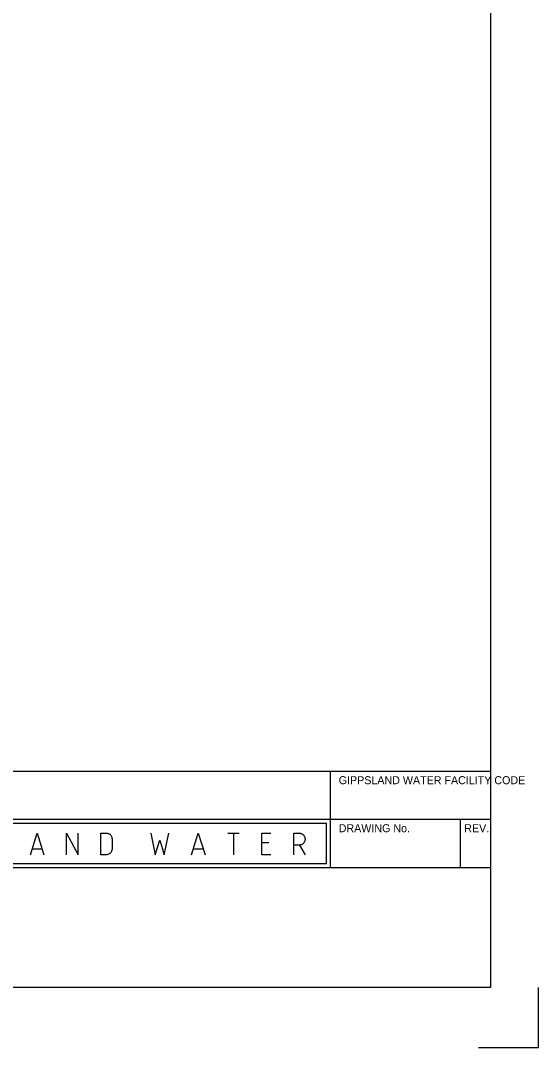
# Model space of a CAD drawing. Extents: x 0 to 841, y 0 to 594.
# Drawn here: x 711.5 to 841, y 0 to 256.6 of the extents above; entities that cross this region are included whole.
import ezdxf

# ---------------------------------------------------------------- set-up
doc = ezdxf.new("R2010")
doc.units = 0
doc.layers.add('A1BORDER', color=7, linetype='Continuous')

msp = doc.modelspace()

# ---------------------------------------------------------------- linework, layer by layer
at = {"layer": 'A1BORDER'}
for p, q in [((829, 581), (829, 15)), ((592.5, 69), (829, 69)), ((789, 45), (789, 69)), ((28, 57), (829, 57)), ((821.5, 45), (821.5, 57)), ((637, 56), (788, 56)), ((788, 46), (788, 56)), ((663, 46), (788, 46)), ((664, 45), (829, 45)), ((829, 15), (28, 15)), ((829, 15), (829, 15)), ((841, 0), (841, 15)), ((826, 0), (841, 0))]:
    msp.add_line(p, q, dxfattribs=at)
for points in [[(713.91, 48.16), (715.61, 53.54), (717.32, 48.16)], [(722.99, 48.16), (722.99, 53.54), (725.83, 48.16), (725.83, 53.54)], [(731.52, 48.16), (731.52, 53.54), (732.94, 53.54), (733.06, 53.54), (733.18, 53.52), (733.3, 53.49), (733.42, 53.45), (733.53, 53.4), (733.64, 53.34), (733.75, 53.27), (733.84, 53.19), (733.94, 53.1), (734.02, 53), (734.09, 52.9), (734.16, 52.79), (734.22, 52.67), (734.27, 52.56), (734.31, 52.43), (734.33, 52.31), (734.35, 52.18), (734.36, 52.05), (734.36, 49.66), (734.35, 49.52), (734.33, 49.39), (734.31, 49.27), (734.27, 49.14), (734.22, 49.02), (734.16, 48.91), (734.09, 48.8), (734.02, 48.7), (733.94, 48.6), (733.84, 48.51), (733.75, 48.43), (733.64, 48.36), (733.53, 48.3), (733.42, 48.25), (733.3, 48.21), (733.18, 48.18), (733.06, 48.16), (732.94, 48.16), (731.52, 48.16)], [(744.01, 53.54), (745.14, 48.16), (746.28, 51.75), (747.41, 48.16), (748.55, 53.54)], [(754.22, 48.16), (755.92, 53.54), (757.63, 48.16)], [(763.31, 53.54), (766.15, 53.54)], [(764.73, 53.54), (764.73, 48.16)], [(774.09, 48.16), (771.82, 48.16), (771.82, 53.54), (774.09, 53.54)], [(779.78, 48.16), (779.78, 53.54), (781.2, 53.54), (781.32, 53.54), (781.44, 53.52), (781.56, 53.49), (781.68, 53.45), (781.79, 53.4), (781.9, 53.34), (782.01, 53.27), (782.1, 53.19), (782.2, 53.1), (782.28, 53), (782.35, 52.9), (782.42, 52.79), (782.48, 52.67), (782.53, 52.56), (782.56, 52.43), (782.59, 52.31), (782.61, 52.18), (782.61, 52.05), (782.61, 51.91), (782.59, 51.78), (782.56, 51.66), (782.53, 51.53), (782.48, 51.42), (782.42, 51.3), (782.35, 51.19), (782.28, 51.09), (782.2, 50.99), (782.1, 50.9), (782.01, 50.82), (781.9, 50.75), (781.79, 50.69), (781.68, 50.64), (781.56, 50.6), (781.44, 50.57), (781.32, 50.55), (781.2, 50.55), (779.78, 50.55)], [(714.48, 49.66), (716.75, 49.66)], [(754.79, 49.66), (757.06, 49.66)], [(773.53, 51.15), (771.82, 51.15)], [(781.2, 50.55), (782.61, 48.16)]]:
    msp.add_lwpolyline(points, dxfattribs=at)

# ---------------------------------------------------------------- texts
for s, p in [('GIPPSLAND WATER FACILITY CODE', (791.03, 65.77)), ('DRAWING No.', (791.03, 53.77)), ('REV.', (822.43, 53.77))]:
    msp.add_text(s, height=2, dxfattribs=at).set_placement(p)

doc.saveas('drawing.dxf')
